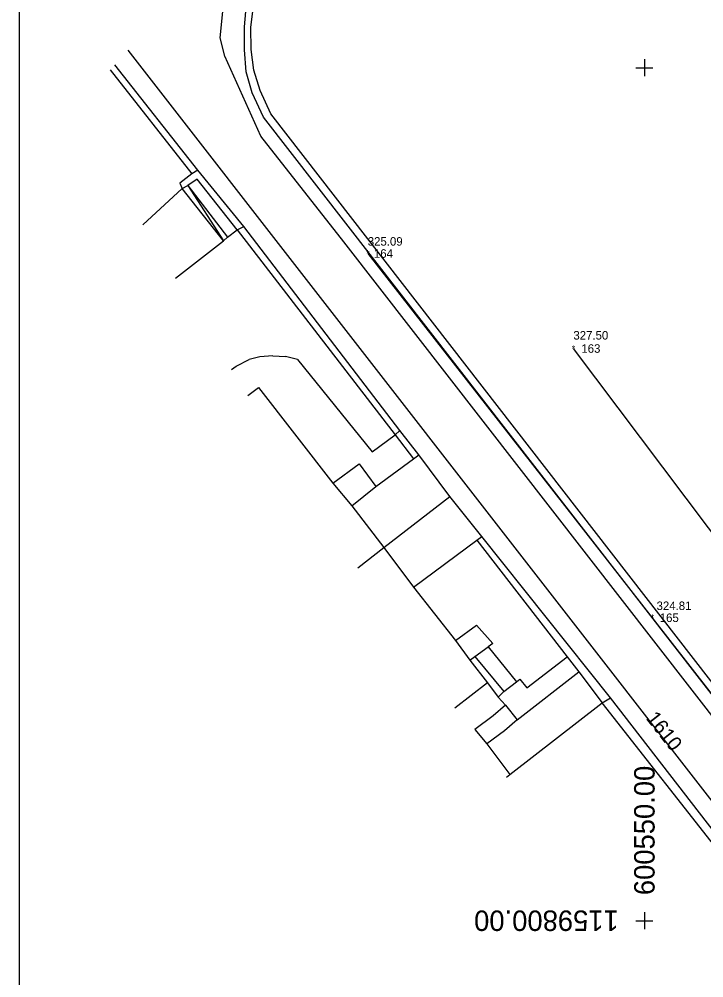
# Model space of a CAD drawing. Extents: x -600587 to -600377, y -1159886 to -1159708.
# Drawn here: x -600586.6 to -600546.5, y -1159803.3 to -1159747.2 of the extents above; entities that cross this region are included whole.
import ezdxf

# ---------------------------------------------------------------- set-up
doc = ezdxf.new("R2010")
doc.units = 0
for name, color, linetype in [('Hranice parcel', 7, 'Continuous'), ('Parcelní čísla', 7, 'Continuous'), ('Vnitřní kresba', 7, 'Continuous'), ('Vrstva 11', 7, 'Continuous'), ('Vrstva 2', 7, 'Continuous'), ('Vrstva 58', 7, 'Continuous'), ('Vrstva 59', 7, 'Continuous'), ('Vrstva 60', 7, 'Continuous'), ('Vrstva 62', 7, 'Continuous'), ('Vrstva 63', 7, 'Continuous'), ('Vrstva 7', 7, 'Continuous')]:
    doc.layers.add(name, color=color, linetype=linetype)

msp = doc.modelspace()

# ---------------------------------------------------------------- linework, layer by layer
at = {"layer": 'Hranice parcel'}
for points in [[(-600488.61, -1159847.98), (-600490.62, -1159848.62), (-600491.99, -1159848.82), (-600493.39, -1159848.77), (-600494.93, -1159848.62), (-600496.36, -1159848.13), (-600500.23, -1159845.75), (-600572.32, -1159752.89), (-600572.98, -1159751.48), (-600573.33, -1159750.24), (-600573.44, -1159748.95), (-600573.44, -1159747.6), (-600573.32, -1159746.25), (-600573.13, -1159744.93), (-600572.66, -1159743.72), (-600571.05, -1159741.4), (-600570.22, -1159740.33), (-600564.67, -1159736.09)], [(-600573.48, -1159759.3), (-600576.16, -1159756.01), (-600581.03, -1159749.824)], [(-600577.474, -1159762.34), (-600574.66, -1159760.14), (-600574.43, -1159759.94), (-600573.86, -1159759.5), (-600573.48, -1159759.3)], [(-600561.39, -1159775.13), (-600563.22, -1159772.7), (-600564.33, -1159771.26), (-600573.48, -1159759.3)], [(-600566.786, -1159779.311), (-600565.26, -1159778.12), (-600561.39, -1159775.13)], [(-600551.99, -1159786.94), (-600559.52, -1159777.48), (-600561.39, -1159775.13)], [(-600558.074, -1159791.578), (-600557.88, -1159791.43), (-600552.47, -1159787.22), (-600551.99, -1159786.94)], [(-600524.43, -1159822.45), (-600525.46, -1159821.09), (-600527.36, -1159818.8), (-600536.8, -1159806.55), (-600551.99, -1159786.94)]]:
    msp.add_lwpolyline(points, dxfattribs=at)
at = {"layer": 'Vnitřní kresba'}
for p, q in [((-600574.86, -1159748.24), (-600574.69, -1159746.5)), ((-600573.07, -1159747.65), (-600572.91, -1159746.37)), ((-600573.05, -1159748.93), (-600573.07, -1159747.65)), ((-600574.58, -1159749.33), (-600574.86, -1159748.24)), ((-600580.267, -1159748.971), (-600497.15, -1159855.9)), ((-600573.52, -1159751.67), (-600574.58, -1159749.33)), ((-600572.88, -1159750.15), (-600573.05, -1159748.93)), ((-600581.296, -1159750.121), (-600576.51, -1159756.22)), ((-600572.52, -1159751.33), (-600572.88, -1159750.15)), ((-600572.2, -1159752.01), (-600572.52, -1159751.33)), ((-600572.47, -1159754.01), (-600573.52, -1159751.67)), ((-600571.89, -1159752.7), (-600572.2, -1159752.01)), ((-600499.96, -1159845.44), (-600571.89, -1159752.7)), ((-600567.61, -1159760.2), (-600572.47, -1159754.01)), ((-600576.16, -1159756.01), (-600576.51, -1159756.22)), ((-600576.51, -1159756.22), (-600577.23, -1159756.77)), ((-600576.21, -1159756.54), (-600576.76, -1159756.9)), ((-600573.86, -1159759.5), (-600576.21, -1159756.54)), ((-600579.399, -1159759.213), (-600577.08, -1159757.08)), ((-600577.23, -1159756.77), (-600577.08, -1159757.08)), ((-600577.08, -1159757.08), (-600576.76, -1159756.9)), ((-600574.66, -1159760.14), (-600577.08, -1159757.08)), ((-600576.76, -1159756.9), (-600574.66, -1159760.14)), ((-600576.76, -1159756.9), (-600574.43, -1159759.94)), ((-600573.86, -1159759.5), (-600564.61, -1159771.51)), ((-600503.93, -1159842.26), (-600567.61, -1159760.2)), ((-600573.92, -1159767.49), (-600573.15, -1159767.11)), ((-600572.53, -1159766.94), (-600573.15, -1159767.11)), ((-600571.78, -1159766.88), (-600572.53, -1159766.94)), ((-600571.78, -1159766.88), (-600571.02, -1159766.92)), ((-600570.32, -1159767.11), (-600571.02, -1159766.92)), ((-600570.32, -1159767.11), (-600565.96, -1159772.51)), ((-600574.184, -1159767.688), (-600573.92, -1159767.49)), ((-600573.243, -1159769.218), (-600572.62, -1159768.74)), ((-600572.62, -1159768.74), (-600568.26, -1159774.36)), ((-600564.61, -1159771.51), (-600564.33, -1159771.26)), ((-600565.96, -1159772.51), (-600564.61, -1159771.51)), ((-600564.61, -1159771.51), (-600563.53, -1159772.93)), ((-600565.73, -1159774.55), (-600563.53, -1159772.93)), ((-600563.53, -1159772.93), (-600563.22, -1159772.7)), ((-600568.26, -1159774.36), (-600566.72, -1159773.21)), ((-600566.72, -1159773.21), (-600565.73, -1159774.55)), ((-600568.26, -1159774.36), (-600567.14, -1159775.68)), ((-600567.14, -1159775.68), (-600565.73, -1159774.55)), ((-600567.14, -1159775.68), (-600565.26, -1159778.12)), ((-600559.82, -1159777.69), (-600559.52, -1159777.48)), ((-600563.52, -1159780.44), (-600559.82, -1159777.69)), ((-600559.82, -1159777.69), (-600554.53, -1159784.54)), ((-600565.26, -1159778.12), (-600563.52, -1159780.44)), ((-600563.52, -1159780.44), (-600561.07, -1159783.58)), ((-600561.07, -1159783.58), (-600559.84, -1159782.68)), ((-600559.84, -1159782.68), (-600558.88, -1159783.75)), ((-600561.07, -1159783.58), (-600560.22, -1159784.72)), ((-600559.93, -1159784.51), (-600559.16, -1159783.95)), ((-600558.88, -1159783.75), (-600559.16, -1159783.95)), ((-600559.16, -1159783.95), (-600557.5, -1159786)), ((-600560.22, -1159784.72), (-600559.93, -1159784.51)), ((-600560.22, -1159784.72), (-600559.19, -1159786.06)), ((-600559.93, -1159784.51), (-600558.23, -1159786.57)), ((-600556.88, -1159786.34), (-600554.53, -1159784.54)), ((-600554.53, -1159784.54), (-600553.85, -1159785.41)), ((-600557.5, -1159786), (-600557.3, -1159785.85)), ((-600557.46, -1159788.23), (-600553.85, -1159785.41)), ((-600557.3, -1159785.85), (-600556.88, -1159786.34)), ((-600553.85, -1159785.41), (-600552.47, -1159787.22)), ((-600559.19, -1159786.06), (-600561.105, -1159787.533)), ((-600559.19, -1159786.06), (-600558.56, -1159786.89)), ((-600558.23, -1159786.57), (-600557.5, -1159786)), ((-600558.56, -1159786.89), (-600558.23, -1159786.57)), ((-600558.56, -1159786.89), (-600558.14, -1159787.36)), ((-600558.14, -1159787.36), (-600558.87, -1159787.99)), ((-600558.14, -1159787.36), (-600557.46, -1159788.23)), ((-600537.12, -1159806.8), (-600552.47, -1159787.22)), ((-600558.87, -1159787.99), (-600559.93, -1159788.79)), ((-600557.46, -1159788.23), (-600558.2, -1159788.86)), ((-600559.93, -1159788.79), (-600559.23, -1159789.63)), ((-600558.2, -1159788.86), (-600559.23, -1159789.63)), ((-600559.23, -1159789.63), (-600557.88, -1159791.43))]:
    msp.add_line(p, q, dxfattribs=at)
at = {"layer": 'Vrstva 11'}
msp.add_lwpolyline([(-600502.72, -1159834.41), (-600509.56, -1159825.58), (-600519.31, -1159812.85), (-600530.48, -1159797.91), (-600554.16, -1159766.46)], dxfattribs=at)
at = {"layer": 'Vrstva 2'}
msp.add_lwpolyline([(-600586.635, -1159886.355), (-600376.635, -1159886.355), (-600376.635, -1159737.855), (-600586.635, -1159737.855)], close=True, dxfattribs=at)
at = {"layer": 'Vrstva 63'}
for p, q in [((-600550, -1159749.5), (-600550, -1159750.5)), ((-600550.5, -1159750), (-600549.5, -1159750)), ((-600550, -1159799.5), (-600550, -1159800.5)), ((-600550.5, -1159800), (-600549.5, -1159800))]:
    msp.add_line(p, q, dxfattribs=at)
at = {"layer": 'Vrstva 7'}
msp.add_lwpolyline([(-600566.21, -1159760.89), (-600549.54, -1159782.24), (-600535.27, -1159800.58), (-600519.17, -1159821.21), (-600501, -1159844.58)], dxfattribs=at)

# ---------------------------------------------------------------- texts
at = {"layer": 'Parcelní čísla'}
msp.add_text('1610', height=0.85, rotation=308, dxfattribs=at).set_placement((-600549.942, -1159788.137))
at = {"layer": 'Vrstva 58'}
for s, p in [('325.09', (-600566.21, -1159760.431)), ('327.50', (-600554.16, -1159765.935)), ('324.81', (-600549.286, -1159781.789))]:
    msp.add_text(s, height=0.5, dxfattribs=at).set_placement(p)
at = {"layer": 'Vrstva 59'}
for s, p in [('164', (-600565.849, -1159761.14)), ('163', (-600553.692, -1159766.71)), ('165', (-600549.099, -1159782.49))]:
    msp.add_text(s, height=0.5, dxfattribs=at).set_placement(p)
at = {"layer": 'Vrstva 60'}
for p in [(-600566.308, -1159761.09), (-600554.258, -1159766.66), (-600549.638, -1159782.44)]:
    msp.add_text('*', height=0.4, dxfattribs=at).set_placement(p)
at = {"layer": 'Vrstva 62'}
for s, rotation, p in [('600550.00', 90, (-600549.4, -1159798.5)), ('1159800.00', 180, (-600551.5, -1159799.4))]:
    msp.add_text(s, height=1.2, rotation=rotation, dxfattribs=at).set_placement(p)

doc.saveas('drawing.dxf')
